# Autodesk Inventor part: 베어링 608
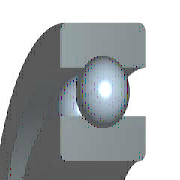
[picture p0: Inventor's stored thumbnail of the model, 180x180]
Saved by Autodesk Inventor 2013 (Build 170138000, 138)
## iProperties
IsCustomPart: 1
Company: 한국ATC센터
Created: 2014-07
Part Number: 베어링 608
Material: Steel, Mild
Description: 깊은 그루브 볼 베어링
Document SubType Name: Modeling
Standard: KS B 2023
Designer: KYOUNG IL JANG
Standards Organization: KS
Language: ko-KR
Size Designation: 608 - 8 x 22 x 7
Categories: <MemberInstance><Categories><Category DisplayName="샤프트 부품" InternalName="7f7aeb1f-a693-4053-b835-cee3144e0d98" Mnemonic="SHFT"><Category DisplayName="베어링" Inter
Density: 1 g/cm^3
Author: KYOUNG IL JANG
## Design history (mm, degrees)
revolve "본체" stored, may be unused: angle "d6" = 90 deg
revolve "볼" stored, may be unused: angle "d7" = 90 deg
pattern_circular "IDS_ARRAYBALL[SIMPL:T]" dims angle "d3" = 360 deg
body "Solid1"
sketch "스케치" dims "d0" = 3.64 (= -0.26 x WD + 0.26 x BD)
  geometry: L1 (1.68, 7.5)-(5.32, 7.5); L2 (3.5, 7.5)-(3.5, 5.68); L3 (3.5, 7.5)-(3.5, 9.32); L4 (2.148, 6.282)-(0, 6.282); L5 (0, 4)-(7, 4); L6 (2.148, 8.718)-(0, 8.718); L7 (0, 11)-(7, 11); L8 (7, 4)-(7, 6.282); L9 (4.852, 6.282)-(7, 6.282); L10 (4.852, 8.718)-(7, 8.718); L11 (7, 11)-(7, 8.718); L12 (-1.4, 0)-(8.4, 0) reference; L13 (0, -0.3)-(0, 5.3) reference
  constraints: 22 end point, 4 point on line, 2 collinear, 2 perpendicular, 2 symmetric about line, 1 midpoint, 1 parallel, 14 other
  dimensions: "d9" = 8 diameter of L5 L12 (= WD); "d11" = 22 diameter of L7 L12 (= BD); "d12" = 7 distance between parallel lines of L8 L13 (= KB); "d13" = 12.564 diameter of L9 L12 (= 0.326 x BD + 0.674 x WD)
fillet "모깎기1" dims "d1" = 0.3 (= KRS)
other parameters: "WD" = 8 [user parameter; used in 5 equation terms], "BD" = 22 [user parameter; used in 5 equation terms], "KB" = 7 [user parameter; used in 1 equation term], "KRS" = 0.3 [user parameter; used in 1 equation term], "d4" = 0, "d5" = 0, "d8" = 0, "d14" = 0, "d15" = 0, "BBA" = 0 [user parameter], "BC0" = 1370000 [user parameter], "BC" = 3250000 [user parameter], "BR" = 11 (= 0.5 x BD) [user parameter], "WR" = 4 (= 0.5 x WD) [user parameter]
